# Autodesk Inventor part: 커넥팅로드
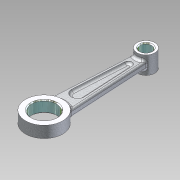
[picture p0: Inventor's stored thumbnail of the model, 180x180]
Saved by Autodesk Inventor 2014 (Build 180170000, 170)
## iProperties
Manager: KYOUNG IL JANG
Company: 한국ATC센터
Created: 2012-10
Part Number: 커넥팅로드
Document SubType Name: Modeling
Density: 1 g/cm^3
Checked By: KYOUNG IL JANG
Vendor: CBT Solutions
Designer: KYOUNG IL JANG
Material: Generic
Appearance: _시험_알루미늄 표면거칠기
Author: KYOUNG IL JANG
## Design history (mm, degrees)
sketch "스케치1"
  geometry: L1 (-19.879, 82.758)-(-19.879, 197.758); L2 (-27.379, 191.144)-(-32.379, 99.633); L3 (-12.379, 191.144)-(-7.379, 99.633); C1 r 14 at (-19.879, 82.758); C2 r 6.5 at (-19.879, 197.758); A1 r 19 centre (-19.879, 82.758) between (-20.11, 101.757) and (-19.649, 63.76) reference; A2 r 21 centre (-19.879, 82.758) between (-32.379, 99.633) and (-7.379, 99.633); A3 r 10 centre (-19.879, 197.758) between (-27.379, 191.144) and (-12.379, 191.144); 1 further point
  constraints: 6 end point, 4 centre point, 4 coincident, 4 point on circle, 2 horizontal alignment, 1 equal length, 1 vertical
  dimensions: "d0" = 28 diameter of C1; "d1" = 42 diameter of A2; "d4" = 115 distance of L1.end C1.centre; "d5" = 20 diameter of A3; "d6" = 13 diameter of C2; "d7" = 25 distance of L3.end L2.end; "d8" = 15 distance of L3.start L2.start
extrude "돌출1" new body sketch "스케치1" stored distance "d2" = 13; taper "d3" = 0 deg
extrude "돌출2" join sketch "스케치1" stored distance "d9" = 20; taper "d10" = 0 deg
extrude "돌출3" join sketch "스케치1" stored distance "d11" = 8; taper "d12" = 0 deg
sketch "스케치2"
  geometry: L1 (7.379, 99.633)-(12.379, 191.144) reference; L2 (27.379, 191.144)-(32.379, 99.633) reference; L3 (27.197, 121.158)-(24.092, 177.989); L4 (15.667, 177.989)-(12.561, 121.158); A1 r 21 centre (19.879, 82.758) between (7.379, 99.633) and (32.379, 99.633) reference; A2 r 7.329 centre (19.879, 120.758) between (12.561, 121.158) and (27.197, 121.158); A3 r 4.219 centre (19.879, 177.758) between (24.092, 177.989) and (15.667, 177.989); A4 r 10 centre (19.879, 197.758) between (12.379, 191.144) and (27.379, 191.144) reference; 2 further points
  constraints: 4 end point, 4 point on circle, 4 tangent, 2 centre point, 2 parallel, 1 coincident, 3 other
  dimensions: "d16" = 38 distance of A2.centre A1.centre; "d17" = 4 distance between parallel lines of L2 L3; "d18" = 4 distance between parallel lines of L4 L1; "d25" = 20 distance of A3.centre A4.centre
extrude "돌출4" cut sketch "스케치2" distance "d19" = 5; taper "d20" = 0 deg
fillet "모깎기1" dims "d21" = 2
fillet "모깎기2" dims "d22" = 3
fillet "모깎기3" dims "d23" = 3
chamfer "모따기1" distance "d26" = 1; stored, may be unused: second distance "d27" = 2, angle "d28" = 45 deg
chamfer "모따기2" distance "d29" = 1; stored, may be unused: second distance "d30" = 2, angle "d31" = 45 deg
node "솔리드1"
mirror "대칭1"
node "참조1"
other parameters: "d13" = 5, "d14" = 5
